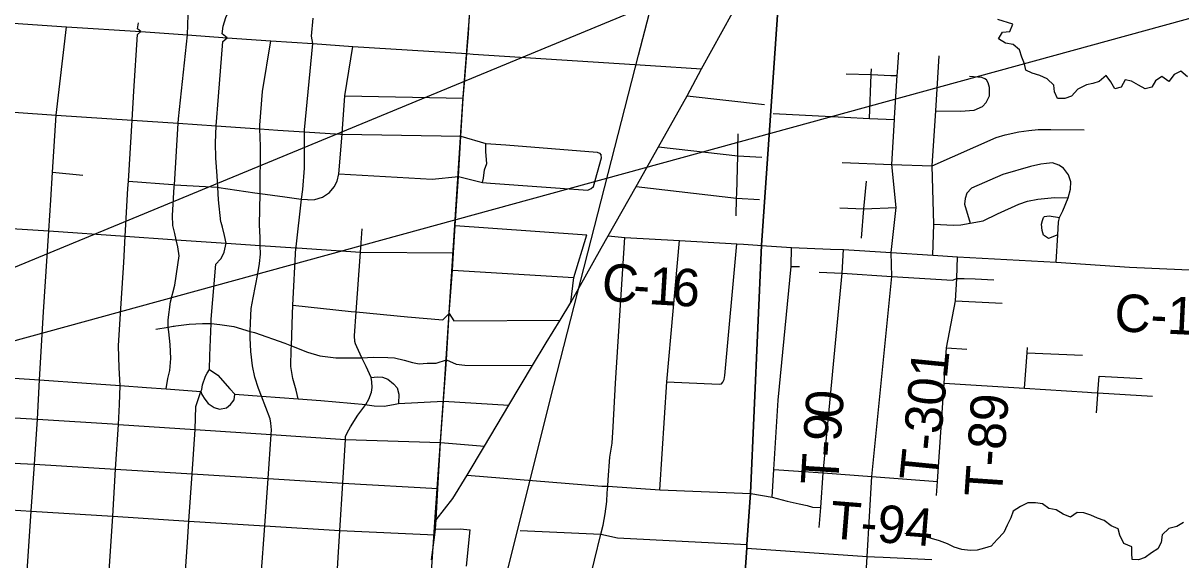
# Model space of a CAD drawing. Extents: x 0 to 34, y 0 to 22.
# Drawn here: x 7.537 to 9.293, y 15.314 to 16.128 of the extents above; entities that cross this region are included whole.
import ezdxf

# ---------------------------------------------------------------- set-up
doc = ezdxf.new("R2010")
doc.units = 0
for name, color, linetype in [('GM_X_City_Street', 7, 'Continuous'), ('GM_X_Corporation', 7, 'Continuous'), ('GM_X_County_Road', 7, 'Continuous'), ('GM_X_County_Road_Text', 7, 'Continuous'), ('GM_X_Minor_River', 7, 'Continuous'), ('GM_X_Rail_Line', 7, 'Continuous'), ('GM_X_State_Route', 7, 'Continuous'), ('GM_X_Township_Road', 7, 'Continuous'), ('GM_X_Township_Road_Text', 7, 'Continuous'), ('SH_Text', 7, 'Continuous')]:
    doc.layers.add(name, color=color, linetype=linetype)

msp = doc.modelspace()

# ---------------------------------------------------------------- linework, layer by layer
at = {"layer": 'GM_X_City_Street'}
for p, q in [((8.0247, 16.0178), (8.2041, 16.0142)), ((8.6746, 15.9911), (8.7825, 15.9852)), ((7.5813, 15.9022), (7.6269, 15.8977)), ((8.1922, 15.8213), (8.2421, 15.8177)), ((8.2421, 15.8177), (8.3916, 15.807)), ((8.1878, 15.7536), (8.3719, 15.7425)), ((8.2092, 15.3048), (8.2147, 15.36))]:
    msp.add_line(p, q, dxfattribs=at)
for points in [[(7.7534, 15.5735), (7.7562, 15.5891), (7.7592, 15.6012), (7.7604, 15.6194), (7.7596, 15.6411), (7.7574, 15.6601), (7.7567, 15.6671), (7.7566, 15.668), (7.7566, 15.6783), (7.76, 15.7056), (7.7665, 15.731), (7.7711, 15.7614), (7.7734, 15.7751), (7.7715, 15.7887), (7.7688, 15.7997), (7.7666, 15.8092), (7.7639, 15.821), (7.7632, 15.8362), (7.7658, 15.8799), (7.766, 15.8831), (7.7719, 15.9761), (7.7723, 15.9827), (7.7857, 16.1102), (7.7876, 16.1555)], [(7.8378, 15.8221), (7.8368, 15.8256), (7.8367, 15.8267), (7.8329, 15.8603), (7.832, 15.8791), (7.831, 15.8964), (7.8289, 15.9234), (7.8285, 15.9466), (7.8296, 15.9722), (7.833, 16.0167), (7.8394, 16.1001), (7.8462, 16.1057), (7.8386, 16.1115), (7.8401, 16.1236), (7.8443, 16.1364), (7.8489, 16.1474)], [(7.661, 15.2018), (7.6632, 15.2357), (7.6678, 15.3047), (7.6725, 15.3805), (7.6769, 15.4518), (7.6812, 15.5198), (7.6825, 15.5499), (7.6838, 15.5785), (7.6822, 15.6057), (7.6814, 15.6387), (7.6839, 15.6797), (7.6892, 15.765), (7.6915, 15.805), (7.6955, 15.8772), (7.6962, 15.8882), (7.702, 15.9808), (7.7045, 16.0247), (7.7103, 16.1107), (7.7152, 16.1151), (7.7101, 16.1195), (7.7114, 16.1285)], [(7.9538, 15.5585), (7.9508, 15.5715), (7.9459, 15.5894), (7.9425, 15.6076), (7.9433, 15.6338), (7.9435, 15.6389), (7.9452, 15.6869), (7.9459, 15.7003), (7.9505, 15.7874), (7.9506, 15.789), (7.9591, 15.8609), (7.9609, 15.876), (7.9632, 15.9079), (7.9632, 15.9632), (7.9632, 15.9663), (7.9759, 16.0969), (7.9739, 16.1083), (7.9766, 16.1353)], [(7.5372, 15.2105), (7.5393, 15.2429), (7.5439, 15.3125), (7.5489, 15.3883), (7.5536, 15.4594), (7.5581, 15.5275), (7.5616, 15.5871), (7.5676, 15.6903), (7.5756, 15.813), (7.5787, 15.8594), (7.5813, 15.9022), (7.5866, 15.9887), (7.6025, 16.1222)], [(7.8976, 15.2902), (7.903, 15.3662), (7.9082, 15.4377), (7.9129, 15.5043), (7.9134, 15.5116), (7.9125, 15.5214), (7.9111, 15.5283), (7.9046, 15.5452), (7.898, 15.5626), (7.8935, 15.5743), (7.8882, 15.5911), (7.8844, 15.6083), (7.8819, 15.63), (7.8809, 15.6509), (7.8811, 15.6607), (7.8814, 15.6736), (7.8826, 15.6952), (7.8853, 15.7115), (7.8925, 15.7478), (7.8952, 15.7637), (7.8966, 15.7777), (7.8963, 15.791), (7.896, 15.8028), (7.8953, 15.8221), (7.8964, 15.8697), (7.8964, 15.8707), (7.8965, 15.9413), (7.8958, 15.9677), (7.8957, 15.9732), (7.8999, 16.0244), (7.9125, 16.101)], [(8.0085, 15.8799), (8.0129, 15.8885), (8.0155, 15.8995), (8.0205, 15.9595), (8.0206, 15.9609), (8.0247, 16.0178), (8.0366, 16.0924)], [(7.5225, 15.993), (7.5866, 15.9887), (7.702, 15.9808), (7.7719, 15.9761), (7.8296, 15.9722), (7.8958, 15.9677), (7.9229, 15.9658), (7.9632, 15.9632), (8.018, 15.9596), (8.0205, 15.9595), (8.2007, 15.9567), (8.2384, 15.9454), (8.269, 15.9435), (8.4074, 15.9323), (8.4112, 15.9307), (8.4134, 15.928)], [(8.2337, 15.8863), (8.2351, 15.8931), (8.2367, 15.9058), (8.2399, 15.9153), (8.2383, 15.9328), (8.2384, 15.9454)], [(8.3981, 15.8771), (8.4019, 15.8804), (8.4139, 15.9238), (8.4134, 15.928)], [(8.0155, 15.8995), (8.1571, 15.8917), (8.1973, 15.8953), (8.2337, 15.8863), (8.2458, 15.8855), (8.3935, 15.8749), (8.3981, 15.8771)], [(7.6962, 15.8882), (7.7636, 15.8832), (7.766, 15.8831), (7.832, 15.8791), (7.8333, 15.879), (7.8881, 15.8709), (7.8964, 15.8697), (7.9335, 15.8645), (7.9584, 15.8609), (7.9591, 15.8609), (7.9682, 15.8604), (7.9702, 15.8603), (7.9793, 15.8605), (7.9907, 15.864), (8.0015, 15.8713), (8.0085, 15.8799)], [(7.5108, 15.8174), (7.5756, 15.813), (7.6915, 15.805), (7.7628, 15.8001), (7.7688, 15.7997), (7.8445, 15.7945), (7.8963, 15.791), (7.9505, 15.7874), (7.9522, 15.7873), (8.0484, 15.7809), (8.1895, 15.7797)], [(7.8322, 15.7662), (7.833, 15.767), (7.837, 15.7713), (7.8414, 15.781), (7.8445, 15.7945), (7.8422, 15.806), (7.8388, 15.8187), (7.8378, 15.8221)], [(8.0124, 15.2832), (8.0147, 15.3182), (8.0171, 15.3591), (8.0214, 15.4308), (8.0254, 15.4968), (8.0258, 15.5016), (8.0282, 15.5069), (8.0331, 15.5162), (8.0443, 15.5337), (8.0564, 15.5498), (8.061, 15.5582), (8.0651, 15.5684), (8.0661, 15.5759), (8.0656, 15.5843), (8.0648, 15.5907), (8.0572, 15.6077), (8.0503, 15.6207), (8.043, 15.6374), (8.0409, 15.6417), (8.0398, 15.6455), (8.0394, 15.6542), (8.0419, 15.6903), (8.0484, 15.7809), (8.0509, 15.816)], [(8.3675, 15.7043), (8.3719, 15.7425), (8.3916, 15.807)], [(8.4242, 15.4355), (8.4268, 15.47), (8.4302, 15.4911), (8.4317, 15.516), (8.4353, 15.5822), (8.4493, 15.8029)], [(8.5025, 15.4204), (8.5129, 15.5841), (8.5323, 15.7983)], [(8.5982, 15.5838), (8.5999, 15.588), (8.6012, 15.594), (8.6191, 15.7935)], [(7.7831, 15.2974), (7.7858, 15.3411), (7.7879, 15.3733), (7.7928, 15.4448), (7.7973, 15.512), (7.7987, 15.5469), (7.8034, 15.562), (7.8063, 15.5697), (7.8075, 15.5728), (7.8089, 15.5796), (7.8131, 15.5928), (7.8159, 15.5972), (7.8191, 15.6032), (7.8198, 15.6241), (7.8216, 15.6729), (7.8219, 15.6795), (7.8291, 15.7628), (7.8322, 15.7662)], [(7.9459, 15.7003), (8.0344, 15.6911), (8.0419, 15.6903), (8.1198, 15.6827), (8.1732, 15.6783), (8.183, 15.6876), (8.19, 15.6769), (8.3512, 15.6779)], [(7.738, 15.6639), (7.7567, 15.6671), (7.7642, 15.6684), (7.7659, 15.6686)], [(7.7659, 15.6686), (7.7684, 15.669), (7.7885, 15.6718), (7.8086, 15.6729), (7.8216, 15.6729), (7.8348, 15.6714), (7.856, 15.668), (7.8811, 15.6607), (7.8875, 15.6589), (7.9334, 15.6429), (7.9435, 15.6389), (7.9679, 15.6292), (7.9865, 15.6235), (8.0112, 15.6208), (8.0442, 15.6204), (8.0503, 15.6207), (8.0674, 15.6216), (8.0901, 15.6212), (8.1, 15.6204), (8.1144, 15.617), (8.1273, 15.6136), (8.1376, 15.6117), (8.1497, 15.6124), (8.1634, 15.6128), (8.1788, 15.6178), (8.1933, 15.6109), (8.2067, 15.6094), (8.3093, 15.6092)], [(7.8191, 15.6032), (7.8317, 15.5945), (7.8501, 15.5737), (7.8578, 15.5655)], [(7.4764, 15.593), (7.5616, 15.5871), (7.6328, 15.5822), (7.6838, 15.5785), (7.7237, 15.5757), (7.7534, 15.5735), (7.8063, 15.5697), (7.8079, 15.5652), (7.812, 15.5579), (7.8175, 15.5512), (7.8264, 15.5453), (7.8346, 15.5429), (7.8453, 15.5447), (7.8512, 15.5498), (7.8567, 15.5568), (7.8578, 15.5655), (7.898, 15.5626), (7.9538, 15.5585), (7.988, 15.556), (8.0564, 15.5498), (8.0584, 15.5496), (8.069, 15.5477), (8.0842, 15.5476), (8.0983, 15.5498), (8.1059, 15.5515), (8.1742, 15.5551), (8.2732, 15.549)], [(8.0648, 15.5907), (8.0738, 15.5916), (8.0818, 15.5914), (8.09, 15.5884), (8.0985, 15.5813), (8.104, 15.5751), (8.1064, 15.5655), (8.1059, 15.5515)], [(8.5129, 15.5841), (8.5925, 15.5806), (8.5959, 15.5813), (8.5982, 15.5838)], [(7.4723, 15.5328), (7.5581, 15.5275), (7.6801, 15.5199), (7.6812, 15.5198), (7.7973, 15.512), (7.9129, 15.5043), (8.0254, 15.4968), (8.1697, 15.4921), (8.2365, 15.4867)], [(7.2778, 15.478), (7.34, 15.4716), (7.4584, 15.4649), (7.5325, 15.4606), (7.5536, 15.4594), (7.6769, 15.4518), (7.7928, 15.4448), (7.9082, 15.4377), (7.9806, 15.4333), (8.0214, 15.4308), (8.1658, 15.4224)], [(8.3475, 14.847), (8.355, 14.9643), (8.3588, 15.0235), (8.3625, 15.0837), (8.3705, 15.1528), (8.3806, 15.2193), (8.3939, 15.2747), (8.413, 15.3532), (8.4165, 15.3672), (8.4197, 15.3843), (8.4219, 15.4028), (8.4226, 15.4159), (8.4235, 15.4262), (8.4242, 15.4355)], [(7.0806, 15.4184), (7.1442, 15.4144), (7.2068, 15.4104), (7.2767, 15.4062), (7.454, 15.3945), (7.5489, 15.3883), (7.5985, 15.3851), (7.6725, 15.3805), (7.7879, 15.3733), (7.903, 15.3662), (8.0171, 15.3591), (8.1614, 15.3524)], [(8.1623, 15.361), (8.1998, 15.3616), (8.2147, 15.36)], [(8.2908, 15.3591), (8.413, 15.3532), (8.4385, 15.3479), (8.6346, 15.3378)]]:
    msp.add_lwpolyline(points, dxfattribs=at)
at = {"layer": 'GM_X_Corporation'}
for points in [[(3.6948, 13.2965), (8.5129, 13.2965), (8.5188, 13.4088), (8.5422, 13.88), (8.5641, 14.2016), (8.5644, 14.2572), (8.5822, 14.5164), (8.5978, 14.7506), (8.6021, 14.8306), (8.6066, 14.8903), (8.6101, 14.9497), (8.614, 15.0091), (8.6169, 15.0685), (8.622, 15.1327), (8.6255, 15.2015), (8.6294, 15.258), (8.6302, 15.2668), (8.6344, 15.3325), (8.6344, 15.3383), (8.6402, 15.4157), (8.6566, 15.7914), (8.6911, 16.2862), (8.7046, 16.4789), (8.7563, 17.3298)], [(8.7563, 17.3298), (8.7046, 16.4789), (8.6911, 16.2862), (8.6566, 15.7914), (8.6402, 15.4157), (8.6344, 15.3383), (8.6344, 15.3325), (8.6302, 15.2668), (8.6294, 15.258), (8.6255, 15.2015), (8.622, 15.1327), (8.6169, 15.0685), (8.614, 15.0091), (8.6101, 14.9497), (8.6066, 14.8903), (8.6021, 14.8306), (8.5978, 14.7506), (8.5822, 14.5164), (8.5644, 14.2572), (8.5641, 14.2016), (8.5422, 13.88), (8.5188, 13.4088), (8.5129, 13.2965), (10.2182, 13.2965)]]:
    msp.add_lwpolyline(points, dxfattribs=at)
at = {"layer": 'GM_X_County_Road'}
for p, q in [((8.2195, 16.0811), (8.4886, 16.0636)), ((8.4886, 16.0636), (8.5655, 16.0586)), ((8.6295, 15.7927), (8.6505, 15.7913)), ((8.9165, 15.7762), (8.9542, 15.7736))]:
    msp.add_line(p, q, dxfattribs=at)
for points in [[(8.212, 16.1117), (8.2134, 16.1318), (8.2175, 16.1815), (8.2175, 16.1889), (8.2233, 16.2548), (8.2263, 16.2774), (8.2316, 16.3106), (8.2385, 16.3451), (8.2413, 16.3568), (8.2582, 16.4008), (8.277, 16.4534), (8.2941, 16.5037), (8.3638, 16.7116), (8.3675, 16.7231)], [(6.8462, 16.1716), (6.9499, 16.1673), (7.0811, 16.1597), (7.1499, 16.1549), (7.2087, 16.1503), (7.2706, 16.1462), (7.3333, 16.1408), (7.3509, 16.14), (7.3936, 16.1368), (7.4583, 16.1326), (7.4919, 16.13), (7.5078, 16.129), (7.536, 16.1269), (7.6025, 16.1222), (7.7152, 16.1151), (7.7857, 16.1102), (7.8462, 16.1057), (7.9125, 16.101), (7.9759, 16.0969), (8.0366, 16.0924), (8.2099, 16.0817), (8.2195, 16.0811)], [(8.2066, 16.0432), (8.2099, 16.0817), (8.212, 16.1117)], [(8.1757, 15.576), (8.1788, 15.6178), (8.183, 15.6876), (8.1878, 15.7536), (8.1895, 15.7797), (8.1922, 15.8213), (8.1973, 15.8953), (8.2007, 15.9567), (8.2041, 16.0142), (8.2066, 16.0432)], [(8.4239, 15.8054), (8.4493, 15.8029), (8.5323, 15.7983), (8.6191, 15.7935), (8.6295, 15.7927)], [(8.6505, 15.7913), (8.6568, 15.7908), (8.7024, 15.7878), (8.7615, 15.7855)], [(8.7615, 15.7855), (8.7812, 15.7847), (8.8537, 15.7803), (8.9165, 15.7762)], [(8.9542, 15.7736), (9.104, 15.7658), (9.215, 15.758), (9.2946, 15.7543), (9.3735, 15.751), (9.3864, 15.7502)], [(8.1633, 15.3749), (8.1658, 15.4224), (8.1697, 15.4921), (8.1742, 15.5551), (8.1757, 15.576)], [(8.627, 15.2198), (8.6296, 15.2575), (8.6305, 15.2662), (8.6346, 15.332), (8.6346, 15.3378), (8.6404, 15.4151)]]:
    msp.add_lwpolyline(points, dxfattribs=at)
at = {"layer": 'GM_X_Minor_River'}
for points in [[(9.0379, 16.1266), (9.0152, 16.1336)], [(9.3029, 16.0466), (9.2927, 16.0551), (9.2828, 16.0499), (9.2748, 16.0397), (9.2642, 16.047), (9.2543, 16.0406), (9.2489, 16.0308), (9.239, 16.0286), (9.2285, 16.0337), (9.2183, 16.0402), (9.2085, 16.0418), (9.2023, 16.0309), (9.1928, 16.0283), (9.1865, 16.039), (9.1797, 16.0486), (9.169, 16.0395), (9.1595, 16.0366), (9.15, 16.0344), (9.1367, 16.0281), (9.1271, 16.0175), (9.1169, 16.0138), (9.1059, 16.0139), (9.1014, 16.0239), (9.1004, 16.0337), (9.0899, 16.0437), (9.0789, 16.0488), (9.0676, 16.0523), (9.0578, 16.0565), (9.0556, 16.0661), (9.0515, 16.0764), (9.0482, 16.0874), (9.0384, 16.0958), (9.027, 16.0975), (9.0161, 16.1044), (9.0226, 16.1142), (9.0336, 16.1153), (9.0379, 16.1266)], [(9.2968, 15.3712), (9.2869, 15.3652), (9.2747, 15.3619), (9.2648, 15.3521), (9.2631, 15.3407), (9.2581, 15.3309), (9.2482, 15.3249), (9.2387, 15.3178), (9.2288, 15.3145), (9.219, 15.315), (9.2187, 15.3245), (9.2184, 15.3343), (9.2067, 15.3394), (9.2003, 15.3516), (9.1981, 15.3615), (9.1872, 15.3658), (9.1767, 15.3742), (9.1665, 15.3777), (9.1566, 15.382), (9.1457, 15.3855), (9.1358, 15.386), (9.1255, 15.3793), (9.1146, 15.3839), (9.104, 15.3901), (9.0927, 15.3921), (9.0829, 15.3994), (9.0723, 15.401), (9.0609, 15.4011), (9.0499, 15.3952), (9.0388, 15.388), (9.035, 15.3782), (9.0295, 15.3669), (9.0245, 15.3559), (9.0142, 15.3454), (9.0054, 15.3352), (8.9951, 15.3323), (8.9837, 15.3293), (8.9731, 15.3287), (8.9606, 15.3299), (8.9493, 15.3335), (8.9387, 15.3385), (8.9266, 15.3432), (8.9149, 15.3467), (8.9039, 15.3491), (8.8926, 15.3518), (8.882, 15.3535), (8.8744, 15.3543)]]:
    msp.add_lwpolyline(points, dxfattribs=at)
at = {"layer": 'GM_X_Rail_Line'}
for points in [[(8.7279, 17.2958), (8.5216, 17.0152), (8.4432, 16.9089), (8.4198, 16.8738), (8.4098, 16.8519), (8.3945, 16.8087), (8.3703, 16.7482), (8.2705, 16.4554), (8.2568, 16.4077), (8.2377, 16.3483), (8.2215, 16.2652), (8.2177, 16.1955), (8.2098, 16.0924), (8.2029, 16.009), (8.1754, 15.5803), (8.1612, 15.3789), (8.1431, 15.1078), (8.132, 15.0859), (7.9202, 14.65), (7.7684, 14.3338), (7.564, 13.9259)], [(7.8762, 13.7771), (7.9514, 14.0592), (8.0586, 14.4862), (8.1542, 14.8606), (8.2278, 15.1245), (8.3419, 15.5786), (8.47, 16.0796), (8.6297, 16.6936), (8.7387, 17.1237), (8.7742, 17.2543)]]:
    msp.add_lwpolyline(points, dxfattribs=at)
at = {"layer": 'GM_X_State_Route'}
for points in [[(8.5655, 16.0586), (8.6913, 16.2856), (8.7268, 16.3476)], [(8.4136, 15.787), (8.4239, 15.8054), (8.4664, 15.8803), (8.5003, 15.9403), (8.5438, 16.018), (8.5655, 16.0586)], [(8.3303, 15.6436), (8.3512, 15.6779), (8.3675, 15.7043), (8.4136, 15.787)], [(8.1633, 15.3749), (8.1883, 15.4075), (8.2101, 15.443), (8.2365, 15.4867), (8.2732, 15.549), (8.3093, 15.6092), (8.3303, 15.6436)], [(8.1563, 15.3145), (8.1614, 15.3524), (8.1623, 15.361), (8.1633, 15.3749)]]:
    msp.add_lwpolyline(points, dxfattribs=at)
at = {"layer": 'GM_X_Township_Road'}
for p, q in [((8.8531, 16.0487), (8.8628, 16.0484)), ((8.5438, 16.018), (8.6611, 16.0047)), ((8.779, 15.9165), (8.8543, 15.9136)), ((8.8543, 15.9136), (8.9158, 15.9115)), ((8.6184, 15.8358), (8.619, 15.8629)), ((8.7016, 15.7593), (8.7143, 15.7589)), ((8.981, 15.7402), (9.0093, 15.7389)), ((8.9512, 15.7068), (8.9715, 15.7058)), ((8.9715, 15.7058), (9.0221, 15.7035)), ((8.9373, 15.6358), (8.9685, 15.6339)), ((9.06, 15.6281), (9.144, 15.6247)), ((9.1672, 15.5677), (9.1691, 15.5929)), ((9.1691, 15.5929), (9.2344, 15.5893)), ((8.6729, 15.4095), (8.6755, 15.4516)), ((8.7466, 15.3937), (8.7504, 15.4462)), ((8.8239, 15.4409), (8.9237, 15.4332)), ((8.922, 15.412), (8.9237, 15.4332)), ((8.6404, 15.4151), (8.6729, 15.4095)), ((8.7444, 15.3633), (8.7466, 15.3937)), ((8.8413, 15.3186), (8.9152, 15.315))]:
    msp.add_line(p, q, dxfattribs=at)
for points in [[(8.8628, 16.0484), (8.8631, 16.0536), (8.865, 16.0833)], [(8.9165, 15.7762), (8.9181, 15.8231), (8.9158, 15.9115), (8.921, 15.9952), (8.9261, 16.0783)], [(8.8208, 15.9836), (8.8233, 16.0499), (8.8236, 16.0588)], [(8.7852, 16.0513), (8.8233, 16.0499), (8.8531, 16.0487)], [(8.8586, 15.982), (8.8587, 15.9842), (8.8628, 16.0484)], [(8.921, 15.9952), (8.9589, 15.9943), (8.9794, 15.9959), (8.9921, 16.0018), (8.9974, 16.0078), (9.0029, 16.0176), (9.0026, 16.0233), (9.0027, 16.0306), (9.0005, 16.0374), (8.9979, 16.042), (8.9956, 16.0436), (8.9911, 16.0455), (8.9725, 16.0473)], [(8.7825, 15.9852), (8.8208, 15.9836), (8.8586, 15.982)], [(8.8537, 15.7803), (8.8611, 15.8484), (8.8543, 15.9136), (8.8586, 15.982)], [(8.9158, 15.9115), (9.0128, 15.9544), (9.0265, 15.9588), (9.0471, 15.9631), (9.0623, 15.9652), (9.0767, 15.9665), (9.0957, 15.9666), (9.1463, 15.9663)], [(8.6206, 15.9269), (8.6209, 15.9374), (8.6214, 15.96)], [(8.5003, 15.9403), (8.6206, 15.9269), (8.6571, 15.925)], [(8.619, 15.8629), (8.6192, 15.8697), (8.6206, 15.9269)], [(9.104, 15.7658), (9.1064, 15.8073), (9.1074, 15.8262), (9.1091, 15.8333), (9.1141, 15.8437), (9.1222, 15.8633), (9.1254, 15.8762), (9.1259, 15.8872), (9.1223, 15.8982), (9.1148, 15.9082), (9.1076, 15.9129), (9.0982, 15.9161), (9.089, 15.9154), (9.0807, 15.9144), (9.065, 15.9108), (9.0231, 15.8984), (8.9753, 15.8778), (8.9684, 15.8703), (8.9656, 15.8623), (8.9648, 15.8536), (8.9731, 15.8248)], [(8.4664, 15.8803), (8.619, 15.8629), (8.6536, 15.8608)], [(8.8083, 15.8021), (8.8122, 15.8464), (8.8159, 15.8883)], [(8.9181, 15.8231), (8.9478, 15.8215), (8.959, 15.8221), (8.9731, 15.8248), (8.9933, 15.8281), (9.0148, 15.8389), (9.0472, 15.8536), (9.0602, 15.858), (9.0762, 15.8609), (9.1013, 15.8636), (9.1222, 15.8633)], [(8.7758, 15.8481), (8.8122, 15.8464), (8.8611, 15.8484)], [(9.1064, 15.8073), (9.0921, 15.8016), (9.0847, 15.8068), (9.0828, 15.8136), (9.0818, 15.8235), (9.0831, 15.8286), (9.0846, 15.8334), (9.0861, 15.8347), (9.0931, 15.8357), (9.1091, 15.8333)], [(8.6755, 15.4516), (8.682, 15.5564), (8.7016, 15.7593), (8.7024, 15.7878)], [(8.7504, 15.4462), (8.7793, 15.7489), (8.7812, 15.7847)], [(8.809, 15.1792), (8.8095, 15.1892), (8.8131, 15.2518), (8.817, 15.3197), (8.8239, 15.4409), (8.8545, 15.744), (8.8537, 15.7803)], [(8.9237, 15.4332), (8.934, 15.5823), (8.9373, 15.6358), (8.9512, 15.7068), (8.9531, 15.7408), (8.9542, 15.7736)], [(8.7441, 15.7506), (8.7793, 15.7489), (8.8545, 15.744), (8.9463, 15.7383), (8.9531, 15.7408), (8.9622, 15.741)], [(8.9622, 15.741), (8.964, 15.7411), (8.981, 15.7402)], [(9.0556, 15.5747), (9.06, 15.6281), (9.0602, 15.6365)], [(8.934, 15.5823), (9.0556, 15.5747), (9.1512, 15.5687), (9.1572, 15.5683)], [(9.1572, 15.5683), (9.1672, 15.5677), (9.25, 15.5625)], [(9.165, 15.5371), (9.167, 15.565), (9.1672, 15.5677)], [(8.2101, 15.443), (8.4147, 15.4262), (8.4235, 15.4262), (8.5025, 15.4204), (8.6404, 15.4151)], [(8.6755, 15.4516), (8.7504, 15.4462), (8.8239, 15.4409)], [(8.6729, 15.4095), (8.6955, 15.4035), (8.7137, 15.3994), (8.7262, 15.3966), (8.7342, 15.3942), (8.7466, 15.3937)], [(8.6346, 15.332), (8.817, 15.3197), (8.8281, 15.3192), (8.8413, 15.3186)]]:
    msp.add_lwpolyline(points, dxfattribs=at)
at = {"layer": 'SH_Text'}
msp.add_lwpolyline([(10.5973, 17.0279), (6.7238, 15.4274), (10.5973, 16.4895)], close=True, dxfattribs=at)

# ---------------------------------------------------------------- texts
at = {"layer": 'GM_X_County_Road_Text'}
for s, height, rotation, p in [('C', 0.0568, 354.3783, (8.4124, 15.7085)), ('1', 0.0568, 356.558, (8.4845, 15.7022)), ('6', 0.0568, 356.677, (8.5196, 15.7001)), ('-', 0.0568, 356.2058, (8.4608, 15.7037)), ('C-16', 0.05682, 357.2584, (9.1912, 15.6611))]:
    msp.add_text(s, height=height, rotation=rotation, dxfattribs=at).set_placement(p)
at = {"layer": 'GM_X_Township_Road_Text'}
for s, height, rotation, p in [('T-301', 0.05682, 84.3731, (8.9226, 15.4325)), ('0', 0.0568, 85.7653, (8.7791, 15.5275)), ('T-89', 0.05682, 86.1043, (9.0213, 15.4085)), ('9', 0.0568, 86.3964, (8.7769, 15.4927)), ('-', 0.0568, 86.4928, (8.7755, 15.4694)), ('T', 0.0568, 86.5223, (8.7729, 15.427)), ('T-94', 0.05682, 355.4108, (8.7592, 15.3473))]:
    msp.add_text(s, height=height, rotation=rotation, dxfattribs=at).set_placement(p)

doc.saveas('drawing.dxf')
